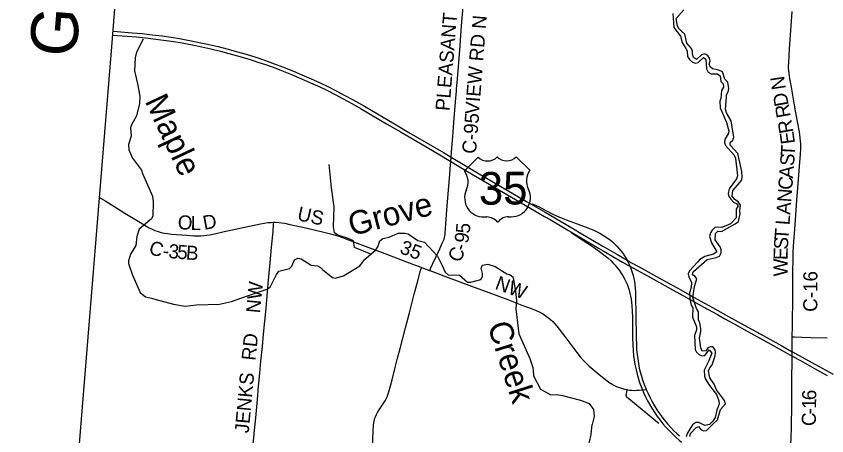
# Model space of a CAD drawing. Extents: x -51392 to 1635000, y 156707 to 696232.
# Drawn here: x 74563 to 91823, y 518897 to 527835 of the extents above; entities that cross this region are included whole.
import ezdxf

# ---------------------------------------------------------------- set-up
doc = ezdxf.new("R2010")
doc.units = 0
for name, color, linetype in [('GM_X_Adjacent_County', 7, 'Continuous'), ('GM_X_Adjacent_County_Text', 7, 'Continuous'), ('GM_X_County', 7, 'Continuous'), ('GM_X_County_Road', 7, 'Continuous'), ('GM_X_County_Road_Text', 7, 'Continuous'), ('GM_X_Major_River', 7, 'Continuous'), ('GM_X_Minor_River', 7, 'Continuous'), ('GM_X_Minor_River_Text', 7, 'Continuous'), ('GM_X_State_Route', 7, 'Continuous'), ('GM_X_Township', 7, 'Continuous'), ('GM_X_Township_Road', 7, 'Continuous'), ('GM_X_Township_Road_Text', 7, 'Continuous'), ('GM_X_US_Route', 7, 'Continuous'), ('GM_X_US_Shield', 7, 'Continuous')]:
    doc.layers.add(name, color=color, linetype=linetype)

msp = doc.modelspace()

# ---------------------------------------------------------------- linework, layer by layer
at = {"layer": 'GM_X_Adjacent_County'}
msp.add_lwpolyline([(74563, 502065), (74862, 505867), (75172, 509582), (75227, 510268), (75674, 515788), (75743, 516628), (75955, 519254), (76337, 523966), (76597, 527182), (76801, 529705), (77124, 533695), (77266, 535451), (77972, 544170), (78206, 547064), (78655, 552615), (78677, 552881), (79341, 561012)], dxfattribs=at)
at = {"layer": 'GM_X_County'}
msp.add_lwpolyline([(74563, 502065), (74862, 505867), (75172, 509582), (75227, 510268), (75674, 515788), (75743, 516628), (75955, 519254), (76337, 523966), (76597, 527182), (76801, 529705), (77124, 533695), (77266, 535451), (77972, 544170), (78206, 547064), (78655, 552615), (80912, 552436), (84311, 552167), (86696, 551986), (89363, 551763), (96623, 551154), (109974, 550151)], dxfattribs=at)
at = {"layer": 'GM_X_County_Road'}
for points in [[(83940, 526285), (83951, 526420), (83985, 526845), (84013, 527205), (84031, 527434), (84053, 527712), (84094, 528202), (84114, 528447), (84149, 528905), (84168, 529134), (84174, 529243)], [(91096, 521531), (91097, 521591), (91100, 521935), (91101, 522164), (91103, 522427), (91105, 522640), (91108, 522804), (91114, 522935), (91147, 523392), (91186, 523916), (91207, 524177), (91242, 524635), (91262, 524897), (91269, 525011), (91271, 525077), (91269, 525126), (91266, 525176), (91258, 525241), (91238, 525371), (91166, 525774), (91129, 525984), (91068, 526323), (91037, 526501), (91020, 526614), (91013, 526679), (91010, 526728), (91010, 526777), (91012, 526842), (91032, 527137), (91045, 527333), (91085, 527938)], [(83713, 523410), (83721, 523510), (83735, 523706), (83761, 524049), (83787, 524376), (83810, 524670), (83816, 524741), (83824, 524833), (83833, 524948), (83860, 525275), (83883, 525570), (83919, 526011), (83937, 526240), (83940, 526285)], [(76340, 523967), (76358, 523957), (76471, 523892), (76638, 523789), (76876, 523642), (77156, 523471), (77310, 523377), (77396, 523329), (77455, 523299), (77515, 523273), (77562, 523255), (77609, 523240), (77673, 523223), (77721, 523213), (77786, 523203), (77868, 523194), (78195, 523169), (78343, 523160), (78425, 523157), (78491, 523158), (78557, 523162), (78622, 523170), (78687, 523180), (78784, 523199), (78960, 523239), (79264, 523306), (79762, 523413), (79842, 523428), (79923, 523439), (79989, 523444), (80037, 523446), (80049, 523446)], [(80049, 523446), (80086, 523445), (80152, 523441), (80217, 523434), (80281, 523424), (80362, 523408), (80730, 523325), (81114, 523237), (81257, 523202), (81336, 523180), (81414, 523155), (81507, 523122), (81767, 523023), (82412, 522779), (82873, 522606), (83180, 522490), (83195, 522484)], [(83367, 522419), (83386, 522462), (83427, 522551), (83581, 522878), (83636, 522997), (83656, 523042), (83672, 523088), (83681, 523119), (83688, 523151), (83695, 523199), (83705, 523313), (83713, 523410)], [(82146, 518669), (82165, 518996), (82173, 519127), (82177, 519177), (82182, 519209), (82189, 519242), (82199, 519273), (82211, 519304), (82232, 519349), (82256, 519393), (82291, 519448), (82393, 519597), (82419, 519639), (82442, 519682), (82462, 519726), (82478, 519772), (82497, 519835), (82565, 520088), (82627, 520327), (82684, 520549), (82739, 520755), (82854, 521199), (82937, 521517), (83011, 521803), (83040, 521914), (83106, 522168), (83162, 522391), (83170, 522422), (83176, 522438), (83182, 522454), (83195, 522484)], [(83195, 522484), (83364, 522420), (83367, 522419)], [(83367, 522419), (83487, 522374), (83764, 522271), (84255, 522086), (84624, 521948), (85009, 521805), (85331, 521683), (85546, 521602), (85637, 521565), (85696, 521537), (85753, 521506), (85809, 521472), (85850, 521444), (85902, 521405), (85939, 521373), (85987, 521329), (86032, 521281), (86075, 521232), (86126, 521168), (86265, 520985), (86502, 520671), (86573, 520580), (86626, 520517), (86682, 520457), (86717, 520422), (86766, 520379), (86841, 520314), (86942, 520230), (87006, 520179), (87121, 520086), (87173, 520046), (87212, 520020)], [(91088, 521008), (91091, 521230), (91094, 521427), (91096, 521531)], [(91075, 519711), (91075, 519771), (91080, 520181), (91083, 520427), (91085, 520597), (91086, 520689), (91086, 520706), (91088, 520968), (91088, 521008)], [(91088, 521008), (91132, 521007), (91288, 521001), (91487, 520994), (91831, 520985)], [(87212, 520020), (87228, 520009), (87271, 519984), (87315, 519961), (87360, 519941), (87406, 519924), (87454, 519909), (87517, 519892), (87574, 519880)], [(87574, 519880), (87582, 519878), (87631, 519871), (87680, 519866), (87729, 519865), (87779, 519866), (87828, 519870), (87896, 519876)], [(87896, 519876), (87977, 519885)], [(91054, 518651), (91058, 518722), (91063, 518853), (91068, 519083), (91076, 519574), (91075, 519711)]]:
    msp.add_lwpolyline(points, dxfattribs=at)
at = {"layer": 'GM_X_Major_River'}
for points in [[(88547, 527893), (88563, 527594), (88707, 527411), (88746, 527273), (88786, 527207), (88818, 527149), (88847, 527097), (88855, 526975), (88897, 526913), (88965, 526853), (89018, 526833), (89083, 526849), (89197, 526952), (89249, 526922), (89260, 526714), (89296, 526644), (89364, 526610), (89496, 526611), (89550, 526565), (89563, 526441), (89617, 526393), (89625, 526323), (89580, 526253), (89566, 526081), (89547, 526026), (89551, 525886), (89581, 525820), (89686, 525574), (89735, 525392), (89727, 525342), (89650, 525212), (89648, 525146), (89666, 525084), (89791, 524940), (89849, 524878), (89877, 524808), (89919, 524434), (89897, 524374), (89746, 524161), (89725, 524060), (89739, 523994), (89779, 523937), (89839, 523873), (89901, 523849), (89938, 523793), (89894, 523723), (89895, 523537), (89769, 523414), (89586, 523333), (89444, 523344), (89380, 523274), (89344, 523220), (89327, 523145), (89365, 523007), (89482, 522816), (89412, 522769), (89225, 522720), (89117, 522650), (89073, 522597), (88900, 522408), (88872, 522344), (88885, 522282), (88941, 522164), (88935, 522058), (88900, 521946), (88905, 521816), (88937, 521682), (88969, 521622), (88962, 521423), (89045, 521221), (89051, 521157), (89004, 521037), (89023, 520735), (89051, 520681), (89111, 520621), (89173, 520599), (89229, 520611), (89321, 520730), (89375, 520658), (89300, 520464), (89213, 520297), (89221, 520169), (89243, 520107), (89324, 519969), (89475, 519779), (89527, 519639), (89533, 519581), (89482, 519445), (89449, 519289), (89397, 519212), (89322, 519135)], [(89245, 520710), (89169, 520701), (89141, 520769), (89114, 520979), (89141, 521124), (89141, 521174), (89121, 521310), (89088, 521360), (89090, 521538), (89047, 521612), (88968, 521844), (89007, 522076), (89057, 522239), (89020, 522293), (88960, 522325), (88976, 522389), (89273, 522654), (89465, 522693), (89540, 522722), (89576, 522794), (89576, 522858), (89550, 522922), (89449, 523072), (89450, 523206), (89506, 523258), (89580, 523249), (89875, 523410), (89941, 523463), (89978, 523625), (89968, 523691), (89984, 523811), (89937, 523879), (89863, 523931), (89805, 524005), (89822, 524125), (89976, 524298), (90011, 524350), (90023, 524412), (90015, 524530), (89925, 524913), (89768, 525090), (89768, 525142), (89824, 525197), (89842, 525259), (89786, 525609), (89686, 525779), (89665, 525853), (89684, 526103), (89690, 526161), (89724, 526221), (89735, 526296), (89715, 526428), (89653, 526496), (89600, 526652), (89524, 526687), (89390, 526715), (89336, 526754), (89319, 526813), (89341, 526885), (89327, 526939), (89287, 526999), (89223, 527036), (89157, 527014), (89045, 526915), (88987, 526955), (88965, 527025), (88966, 527091), (88940, 527145), (88842, 527263), (88799, 527449), (88729, 527517), (88669, 527573), (88642, 527623), (88616, 527783), (88779, 527970)], [(89386, 519135), (89497, 519237), (89560, 519461), (89663, 519580), (89641, 519646), (89474, 519877), (89424, 519995), (89331, 520129), (89303, 520281), (89330, 520347), (89382, 520408), (89443, 520598), (89455, 520675), (89443, 520725), (89393, 520790), (89341, 520794), (89289, 520772), (89245, 520710)], [(89322, 519135), (89229, 519118), (89101, 519178), (89033, 519179), (88966, 519129), (88852, 518946), (88828, 518876)], [(88906, 518883), (88923, 518949), (89034, 519064), (89090, 519096), (89148, 519026), (89204, 519005), (89258, 519013), (89386, 519135)]]:
    msp.add_lwpolyline(points, dxfattribs=at)
at = {"layer": 'GM_X_Minor_River'}
for points in [[(77263, 527348), (77121, 527072), (77093, 526951), (77081, 526673), (77145, 526392), (77195, 526134), (77191, 525974), (77127, 525713), (77015, 525523), (76995, 525457), (77013, 525278), (76955, 525102), (76961, 524986), (77039, 524811), (77233, 524553), (77255, 524483), (77464, 524000), (77480, 523882), (77474, 523583), (77440, 523519), (77181, 523301), (77129, 523146), (77107, 522954), (76995, 522764), (76951, 522626), (76953, 522569), (77037, 522321), (77205, 521952), (77317, 521860), (77446, 521826), (77514, 521810), (77910, 521699), (78162, 521661), (78405, 521687), (78891, 521703), (79148, 521755), (79346, 521829), (79920, 522027), (79975, 522081), (80103, 522331), (80155, 522401), (80385, 522459), (80431, 522513), (80491, 522646), (80557, 522678), (80627, 522670), (80840, 522535), (80978, 522519), (81040, 522479), (81094, 522431), (81294, 522269), (81352, 522252), (81532, 522304), (81881, 522521), (81933, 522587), (81967, 522639), (82219, 522857), (82263, 522925), (82303, 523047), (82367, 523097), (82506, 523125), (82696, 523211), (82772, 523217), (82846, 523213), (82908, 523199), (83114, 523055), (83258, 523019), (83535, 522726), (83635, 522526), (83695, 522385), (83759, 522327), (83999, 522319), (84174, 522173), (84244, 522169), (84456, 522229), (84494, 522281), (84494, 522353), (84466, 522471), (84490, 522535), (84608, 522551), (84764, 522503), (85009, 522345), (85081, 522329), (85135, 522280), (85149, 522220), (85195, 521974), (85213, 521777), (85199, 521605), (85235, 521301), (85263, 521066), (85497, 520545), (85561, 520355), (85571, 520297), (85577, 520178), (85729, 519890), (85946, 519773), (86064, 519779), (86196, 519757), (86577, 519659)], [(82115, 522763), (81765, 522909), (81745, 523048), (81614, 523106), (81410, 523168), (81342, 523218), (81322, 523352), (81334, 523771), (81276, 524180), (81224, 524675)], [(86577, 519659), (86761, 519583), (86854, 519457), (86866, 519307), (86825, 519141)], [(87360, 517072), (87223, 517182), (87071, 517381), (86890, 517537), (86776, 517668), (86698, 517877), (86688, 517997), (86720, 518187), (86700, 518580), (86709, 518642), (86768, 518770), (86807, 518924), (86825, 519141)]]:
    msp.add_lwpolyline(points, dxfattribs=at)
at = {"layer": 'GM_X_State_Route'}
for points in [[(85528, 523832), (85542, 523835), (85552, 523834), (85567, 523830), (85681, 523781), (85857, 523686), (85974, 523627), (86064, 523585), (86169, 523539), (86276, 523497), (86507, 523412), (86737, 523326), (86843, 523283), (86918, 523249), (86991, 523213), (87047, 523180), (87103, 523145), (87156, 523108), (87208, 523068), (87258, 523026), (87306, 522981), (87352, 522935), (87397, 522887), (87438, 522837), (87478, 522785), (87515, 522731), (87549, 522676), (87570, 522638), (87581, 522619), (87610, 522560), (87632, 522510), (87636, 522500), (87660, 522439), (87680, 522377), (87698, 522314), (87713, 522251), (87725, 522186), (87734, 522122), (87743, 522040), (87748, 521959), (87752, 521844), (87756, 521500), (87764, 520975), (87768, 520844), (87774, 520729), (87783, 520631), (87796, 520534), (87812, 520436), (87831, 520340), (87850, 520260), (87876, 520165), (87901, 520086), (87933, 519993), (87970, 519902), (87977, 519885), (88009, 519811), (88059, 519708), (88104, 519620), (88153, 519535), (88205, 519451), (88260, 519369), (88308, 519303), (88359, 519238), (88433, 519150), (88499, 519077), (88567, 519006), (88626, 518949), (88688, 518894)], [(86374, 523241), (86375, 523237), (86379, 523229), (86388, 523220), (86399, 523211), (86730, 523000), (86852, 522916), (86985, 522820), (87076, 522750), (87166, 522678), (87228, 522624), (87275, 522578), (87319, 522529), (87362, 522478), (87401, 522426), (87439, 522372), (87474, 522316), (87506, 522258), (87542, 522185), (87569, 522124), (87592, 522063), (87613, 522000), (87630, 521936), (87645, 521872), (87656, 521807), (87665, 521742), (87673, 521660), (87678, 521562), (87682, 521414), (87685, 521132)], [(87685, 521132), (87687, 520971), (87691, 520856), (87700, 520709), (87709, 520611), (87722, 520514), (87738, 520417), (87761, 520304), (87784, 520209), (87806, 520130), (87837, 520036), (87883, 519909), (87896, 519876)], [(87896, 519876), (87927, 519803), (87962, 519730), (88006, 519642), (88045, 519570), (88096, 519486), (88158, 519389), (88214, 519308), (88273, 519229), (88334, 519152), (88387, 519090), (88442, 519030), (88534, 518936), (88605, 518868), (88679, 518803), (88730, 518762)]]:
    msp.add_lwpolyline(points, dxfattribs=at)
at = {"layer": 'GM_X_Township'}
msp.add_lwpolyline([(75743, 516628), (75955, 519254), (76337, 523966), (76597, 527182), (76801, 529705), (77124, 533695), (77266, 535451), (77972, 544170)], dxfattribs=at)
at = {"layer": 'GM_X_Township_Road'}
for points in [[(79589, 518487), (79595, 518545), (79609, 518709), (79644, 519086), (79664, 519282), (79700, 519673), (79725, 519951), (79750, 520229), (79775, 520490), (79805, 520800), (79830, 521061), (79883, 521616), (79905, 521877), (79929, 522138), (79970, 522579), (79999, 522906), (80031, 523249), (80044, 523396), (80049, 523446)], [(88243, 519159), (88218, 519180), (87849, 519484), (87607, 519682), (87570, 519713), (87564, 519719), (87560, 519725), (87557, 519732), (87555, 519739), (87554, 519746), (87554, 519753), (87567, 519834), (87574, 519880)]]:
    msp.add_lwpolyline(points, dxfattribs=at)
at = {"layer": 'GM_X_US_Route'}
for points in [[(76626, 527515), (76713, 527509), (77033, 527483), (77246, 527464), (77458, 527441), (77669, 527415), (77864, 527387), (78042, 527358), (78251, 527319), (78460, 527278), (78669, 527232), (78860, 527187), (79051, 527139), (79272, 527078), (79461, 527023), (79664, 526959), (79851, 526897), (80021, 526837), (80236, 526755), (80464, 526665), (80646, 526589), (80841, 526504), (81020, 526422), (81197, 526336), (81388, 526241), (81562, 526149), (81720, 526063), (81976, 525916), (82656, 525518), (82925, 525360), (83660, 524929), (83824, 524833), (84424, 524480), (85428, 523890), (85528, 523832), (85825, 523659), (86391, 523327), (86631, 523186), (87055, 522935), (87353, 522763), (87570, 522638), (87652, 522592), (87824, 522496), (88325, 522217), (88713, 522003), (89000, 521845), (89388, 521630), (89733, 521440), (90077, 521249), (90407, 521066), (90866, 520812), (91086, 520689), (91095, 520684), (91569, 520421), (91956, 520207)], [(76620, 527431), (77121, 527393), (77317, 527374), (77480, 527356), (77756, 527319), (77919, 527295), (78097, 527265), (78307, 527225), (78515, 527183), (78708, 527140), (78915, 527089), (79090, 527043), (79326, 526976), (79546, 526910), (79687, 526866), (79889, 526797), (80090, 526725), (80244, 526667), (80426, 526593), (80638, 526504), (80878, 526398), (81027, 526329), (81189, 526250), (81365, 526161), (81510, 526085), (81726, 525965), (81911, 525859), (82448, 525544), (82760, 525362), (83184, 525113), (83581, 524880), (83779, 524764), (83816, 524741), (84173, 524528), (84683, 524231), (85192, 523932), (85809, 523572)], [(85809, 523572), (85929, 523502), (86325, 523270), (86374, 523241)], [(86374, 523241), (86962, 522896), (87061, 522839), (87472, 522599), (87586, 522535), (87632, 522510), (87788, 522425), (88017, 522297), (88260, 522161), (88548, 522002), (88835, 521844)], [(88835, 521844), (88978, 521765), (89208, 521637), (89495, 521478), (89652, 521390), (89853, 521279), (90126, 521128), (90628, 520849), (90987, 520651), (91085, 520597), (91260, 520501), (91561, 520333), (91833, 520181)]]:
    msp.add_lwpolyline(points, dxfattribs=at)
at = {"layer": 'GM_X_US_Shield'}
for p, q in [((84397, 524833), (84110, 524540)), ((85502, 524553), (85209, 524841)), ((84525, 523558), (84583, 523559)), ((85047, 523563), (85105, 523563))]:
    msp.add_line(p, q, dxfattribs=at)
for centre, radius, start, end in [((84598, 525042), 290, 226.1115, 314.9656), ((85004, 525046), 290, 226.1115, 314.9656), ((83779, 524304), 406, 335.0857, 35.5395), ((85836, 524324), 406, 145.5376, 205.9914), ((84517, 523964), 406, 155.3705, 271.1768), ((85106, 523969), 406, 269.9003, 25.7066), ((84586, 523268), 290, 37.4084, 90.5385), ((85050, 523273), 290, 90.5385, 143.6686)]:
    msp.add_arc(centre, radius, start, end, dxfattribs=at)

# ---------------------------------------------------------------- texts
at = {"layer": 'GM_X_Adjacent_County_Text'}
msp.add_text('GREENE COUNTY', height=1000, rotation=85.3552, dxfattribs=at).set_placement((75838, 526946))
at = {"layer": 'GM_X_County_Road_Text'}
for s, rotation, p in [('PLEASANT', 85.4402, (83787, 525809)), ('VIEW RD N', 85.4393, (84415, 525733)), ('N', 98.7042, (90953, 526291)), ('D', 100.0369, (91014, 525942)), ('R', 100.0349, (91057, 525699)), ('C-95', 85.4057, (84353, 524895)), ('R', 100.0411, (91116, 525366)), ('E', 97.637, (91148, 525130)), ('T', 86.8688, (91139, 524844)), ('S', 85.7264, (91123, 524636)), ('A', 85.6904, (91103, 524373)), ('C', 85.6893, (91085, 524127)), ('N', 85.6914, (91065, 523864)), ('A', 85.6941, (91045, 523600)), ('US', 347.5429, (80530, 523494)), ('O', 355.2345, (77992, 523305)), ('L', 358.6065, (78274, 523282)), ('D', 10.6543, (78567, 523282)), ('L', 85.6893, (91028, 523377)), ('5', 85.6814, (84220, 523199)), ('9', 79.075, (84180, 522981)), ('T', 85.7674, (91005, 523061)), ('C', 342.6306, (77366, 522781)), ('3', 355.3222, (77797, 522685)), ('35', 339.2528, (82709, 522796)), ('S', 86.5345, (90992, 522860)), ('-', 355.7545, (77675, 522694)), ('5', 355.4542, (77982, 522670)), ('B', 355.8167, (78169, 522655)), ('C', 66.0981, (84013, 522570)), ('-', 68.6937, (84119, 522809)), ('E', 88.3396, (90986, 522638)), ('W', 90.284, (90988, 522293)), ('NW', 339.6474, (84740, 522032)), ('C-16', 89.852, (91621, 521537)), ('6', 89.2051, (91597, 519654)), ('1', 89.1231, (91594, 519470)), ('C', 88.9807, (91588, 519103)), ('-', 89.0328, (91592, 519348))]:
    msp.add_text(s, height=300, rotation=rotation, dxfattribs=at).set_placement(p)
at = {"layer": 'GM_X_Minor_River_Text'}
for s, height, rotation, p in [('Maple', 499.9, 295.2255, (77294, 526028)), ('Grove', 500, 14.9031, (81708, 523147)), ('Creek', 499.9, 287.7509, (84594, 521250))]:
    msp.add_text(s, height=height, rotation=rotation, dxfattribs=at).set_placement(p)
at = {"layer": 'GM_X_Township_Road_Text'}
for s, rotation, p in [('NW', 84.4228, (79753, 521500)), ('RD', 84.1976, (79657, 520490)), ('JENKS', 84.7807, (79513, 518945))]:
    msp.add_text(s, height=300, rotation=rotation, dxfattribs=at).set_placement(p)
at = {"layer": 'GM_X_US_Shield'}
msp.add_text('35', height=696.1, rotation=0.5385, dxfattribs=at).set_placement((84416, 523818))

doc.saveas('drawing.dxf')
